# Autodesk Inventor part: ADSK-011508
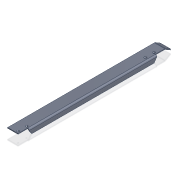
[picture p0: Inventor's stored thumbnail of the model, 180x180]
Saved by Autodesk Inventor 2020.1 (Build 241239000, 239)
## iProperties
Created: 2000-02
Part Number: ADSK-011508
Material: 1.0312 DC05
Description: FSHTPH,SS,CP,01,018,008,239,090,GUIDE,TRANSFER
Document SubType Name: Tôlerie
Designer: sspink
Density: 1 g/cm^3
Sheet Metal Rule: Stahlblech 1.0312 - DC05 -   3.0 mm
Appearance: Metal-Stainless steel-1
Mass: 110.591 g
Surface Area: 778.993 cm^2
Volume: 110.591 cm^3
Flat Pattern Width: 6.44608 cm
Flat Pattern Length: 60.7785 cm
Flat Pattern Area: 391.783 cm^2
Sheet Metal Width: 64,461 mm
Sheet Metal Length: 607,785 mm
Sheet Metal Area: 39178,302 mm^2
Control State: 0
Master: False
Checked Out: False
Shininess: 57.0
Length Units: 11269
Angle Units: 11279
Time Units: 11290
Mass Units: 11283
Length Display Precision: 3
Angle Display Precision: 2
Compacted: True
Cutlength: 2.53 X 24.03 (61 SI)
Material Desc: SHEET,S/S, 11 GA
Material_number: A084638
G_L: 607,8x64,5 mm
Thickness: 3,000 mm
Dimensions: 47,6x22,1x607,8 mm
Mass: 0,111 kg
Semi finished: Stahlblech 1.0312 - DC05 -   3.0 mm
DocNumber: ADSK-011508.ipt
Folder: 01 - Themengebiete\Simplification\04-Packaging machine\
VDS_Category: 3D Komponenten
Density: 0.0
Volumn: 0.0
Area: 0.0
PropertySet Name: Model Information
Author: sspink
Revision Number: -
Title: rail
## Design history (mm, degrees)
node "Solide1"
  node "Extrusion1" dims "d2" = 584.2, "d3" = 0
  node "Face1"
  node "Bend2" dims "d51" = 3 (= BendRadius), "d55" = 3 (= BendReliefWidth), "d56" = 1.5 (= BendReliefDepth), "d57" = 6 (= MinimumRemnant), "d58" = 3 (= Thickness), "SeamGap" = 0.00508, "MinimumRemnant" = 6 (= 2 x Thickness), "BendReliefWidth" = 3 (= Thickness)
  node "Extrusion5" dims "d25" = 41.275, "d26" = 0
  node "Fillet5" dims "d27" = 6 (= BendRadius + Thickness)
  node "Fillet6" dims "d28" = 3 (= Thickness)
  node "Hole1" dims "d35" = 4.5, "d36" = 9.4, "d37" = 6.35, "d38" = 90 deg, "d39" = 19.05, "d40" = 118 deg, "d63" = 6
sketch "Sketch1"
  geometry: L1 (0, 0)-(41.275, 0); L2 (41.275, 0)-(41.275, 3); L3 (41.275, 3)-(0, 3); L4 (0, 3)-(0, 0)
  constraints: 8 end point, 2 parallel, 1 horizontal, 1 perpendicular
  dimensions: "d0" = 3 distance between parallel lines of L1 L3 (= Thickness); "d1" = 41.275 distance between parallel lines of L2 L4
workplane "Work Plane1"
node "Plate1" dims "d50" = 3 (= BendRadius), "d58" = 3 (= Thickness), "MinimumRemnant" = 6 (= 2 x Thickness), "BendReliefWidth" = 3 (= Thickness)
node "Bend1" dims "d50" = 3 (= BendRadius), "d52" = 3 (= BendReliefWidth), "d53" = 1.5 (= BendReliefDepth), "d54" = 6 (= MinimumRemnant), "d58" = 3 (= Thickness), "SeamGap" = 0.00508, "MinimumRemnant" = 6 (= 2 x Thickness), "BendReliefWidth" = 3 (= Thickness)
sketch "Sketch6"
  geometry: L1 (0, 0)-(41.275, 0) reference; L2 (41.275, 34.925)-(41.275, 0) reference; 4 further points
  constraints: 3 vertical alignment
  dimensions: "d31" = 34 distance of point (33.275, 42) point (33.275, 8); "d34" = 34 distance of point (33.275, 515) point (33.275, 549) (= d31); "d59" = 8 distance from line of L1 point (33.275, 8); "d61" = 473 distance of point (33.275, 42) point (33.275, 515); "d62" = 8 distance from line of L2 point (33.275, 8)
node "Corps solides"
node "Corps surfaciques"
sketch "Sketch3"
  geometry: L1 (38.1, 3)-(546.1, 3); L2 (38.1, -3.35)-(38.1, 3); L3 (546.1, 3)-(546.1, -3.35); L4 (38.1, -3.35)-(49.093, -19.05); L5 (49.093, -19.05)-(535.107, -19.05); L6 (535.107, -19.05)-(546.1, -3.35); L7 (0, 3)-(0, 0) reference; L8 (584.2, 0)-(0, 0) reference; L9 (584.2, 3)-(0, 3) reference; L10 (584.2, 0)-(584.2, 3) reference
  constraints: 12 end point, 1 collinear, 1 parallel, 1 perpendicular
  dimensions: "d42" = 6.35 distance of L2.start L1.start; "d43" = 38.1 distance between parallel lines of L7 L2; "d44" = 35 deg angle of L4 L2; "d46" = 19.05 distance between parallel lines of L8 L5; "d47" = 6.35 distance of L1.end L3.end; "d48" = 38.1 distance between parallel lines of L3 L10; "d49" = 35 deg angle of L6 L3
sketch "Sketch5"
  geometry: L1 (0, 0)-(-38.1, 0) reference; L2 (0, 0)-(0, 3) reference; L3 (0, 0)-(21.997, -12.7); L4 (21.997, -12.7)-(23.585, -9.95); L5 (23.585, -9.95)-(1.154, 3); L6 (0, 3)-(1.154, 3); 1 further point; 1 other entity
  constraints: 8 end point, 1 horizontal, 1 parallel, 1 perpendicular, 1 other
  dimensions: "d22" = 25.4 distance of L1.start L3.end; "d23" = 3.175 distance between parallel lines of L5 L3 (= thickness); "d24" = 150 deg angle of L3 L1
feature "Definition1"
other parameters: "thickness" = 3.175 [user parameter; used in 1 equation term], "Thickness" = 3 (derived), "BendRadius" = 3 (= Thickness), "BendReliefDepth" = 1.5 (= 0.5 x Thickness), "CornerReliefSize" = 12 (= 4 x Thickness), "d41" = 6.35, "TransitionRadius" = 3 (= BendRadius), "TailleRayonJacobi" = 3 (= BendRadius), "TailleJeu" = 3 (= Thickness), "thickness" = 3.175, "BendRadius" = 3, "BendReliefDepth" = 1.5, "BendReliefWidth" = 3, "CornerReliefSize" = 12, "MinimumRemnant" = 6, "TailleJeu" = 3, "TailleRayonJacobi" = 3, "Thickness" = 3, "TransitionRadius" = 3
